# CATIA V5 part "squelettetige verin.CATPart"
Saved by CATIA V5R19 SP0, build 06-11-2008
Part number: squelette tige verin
Bounding box of the stored display mesh (mm): x 0 to 0, y 0 to 13, z -14 to 9
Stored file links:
  C:\Users\Gauthier\Documents\IFMA\IAO\TP2\squelettetige verin.CATPart
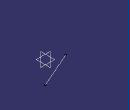
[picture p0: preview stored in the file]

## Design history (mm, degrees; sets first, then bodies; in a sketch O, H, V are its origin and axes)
Line1: type PtPt, SecondPoint Point3, FirstPoint Point1
Line2: stored without definition
Set1
  Point1 to Point3: stored without definition
Body1 (main body)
